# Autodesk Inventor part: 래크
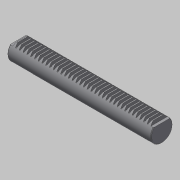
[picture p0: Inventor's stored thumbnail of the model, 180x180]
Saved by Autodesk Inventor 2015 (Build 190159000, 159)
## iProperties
Created: 2019-06
Part Number: 래크
Material: 스테인리스강
Document SubType Name: Modeling
Designer: mduedu
Density: 8.08 g/cm^3
Appearance: 기본값
Mass: 1739.85 g
Surface Area: 334.124 cm^2
Volume: 215.328 cm^3
Author: mduedu
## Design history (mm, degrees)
sketch "스케치1"
  geometry: L1 (0, 0)-(240, 0); L2 (240, 0)-(240, 34); L3 (240, 34)-(0, 34); L4 (0, 34)-(0, 0)
  constraints: 8 end point, 2 parallel, 1 horizontal, 1 perpendicular
  dimensions: "d0" = 240 distance of L1.start L1.end; "d1" = 34 distance of L1.end L2.end
extrude "돌출1" new body sketch "스케치1" stored distance "d2" = 36; taper "d3" = 0 deg
sketch "스케치2"
  geometry: L1 (0, 0)-(240, 0) reference; L2 (240, 0)-(240, 34) reference; L3 (240, 34)-(0, 34) reference; L4 (0, 34)-(0, 0) reference; L5 (9.44, 29.5)-(10.76, 29.5); L6 (12.398, 34)-(7.802, 34); L7 (10.1, 34)-(10.1, 29.5); L8 (7.802, 34)-(9.44, 29.5); L9 (12.398, 34)-(10.76, 29.5); L10 (8.53, 32)-(11.67, 32); 1 further point
  constraints: 12 end point, 2 midpoint, 2 point on line, 1 collinear, 1 horizontal, 1 parallel, 1 perpendicular, 1 symmetric about line
  dimensions: "d4" = 20 deg angle of L9 L7; "d5" = 2 distance between parallel lines of L10 L6; "d7" = 4.5 distance between parallel lines of L5 L6 (= 2.25 x d5); "d8" = 3.14 distance of L10.start L10.end; "d9" = 10.1 distance between parallel lines of L4 L7
extrude "돌출2" cut sketch "스케치2" stored distance "d10" = 36; taper "d11" = 0 deg
sketch "스케치3"
  geometry: L1 (235.52, 29.5)-(233.882, 34) reference; L2 (233.882, 34)-(232.198, 34) reference; L3 (232.198, 34)-(230.56, 29.5) reference; L4 (230.56, 29.5)-(229.24, 29.5) reference; L5 (229.24, 29.5)-(227.602, 34) reference; L6 (227.602, 34)-(225.918, 34) reference; L7 (225.918, 34)-(224.28, 29.5) reference; L8 (224.28, 29.5)-(222.96, 29.5) reference; L9 (222.96, 29.5)-(221.322, 34) reference; L10 (221.322, 34)-(219.638, 34) reference; L11 (219.638, 34)-(218, 29.5) reference; L12 (218, 29.5)-(216.68, 29.5) reference; L13 (216.68, 29.5)-(215.042, 34) reference; L14 (215.042, 34)-(213.358, 34) reference; L15 (213.358, 34)-(211.72, 29.5) reference; L16 (211.72, 29.5)-(210.4, 29.5) reference; L17 (210.4, 29.5)-(208.762, 34) reference; L18 (208.762, 34)-(207.078, 34) reference; L19 (207.078, 34)-(205.44, 29.5) reference; L20 (205.44, 29.5)-(204.12, 29.5) reference; L21 (204.12, 29.5)-(202.482, 34) reference; L22 (202.482, 34)-(200.798, 34) reference; L23 (200.798, 34)-(199.16, 29.5) reference; L24 (199.16, 29.5)-(197.84, 29.5) reference; L25 (197.84, 29.5)-(196.202, 34) reference; L26 (196.202, 34)-(194.518, 34) reference; L27 (194.518, 34)-(192.88, 29.5) reference; L28 (192.88, 29.5)-(191.56, 29.5) reference; L29 (191.56, 29.5)-(189.922, 34) reference; L30 (189.922, 34)-(188.238, 34) reference; L31 (188.238, 34)-(186.6, 29.5) reference; L32 (186.6, 29.5)-(185.28, 29.5) reference; L33 (185.28, 29.5)-(183.642, 34) reference; L34 (183.642, 34)-(181.958, 34) reference; L35 (181.958, 34)-(180.32, 29.5) reference; L36 (180.32, 29.5)-(179, 29.5) reference; L37 (179, 29.5)-(177.362, 34) reference; L38 (177.362, 34)-(175.678, 34) reference; L39 (175.678, 34)-(174.04, 29.5) reference; L40 (174.04, 29.5)-(172.72, 29.5) reference; L41 (172.72, 29.5)-(171.082, 34) reference; L42 (171.082, 34)-(169.398, 34) reference; L43 (169.398, 34)-(167.76, 29.5) reference; L44 (167.76, 29.5)-(166.44, 29.5) reference; L45 (166.44, 29.5)-(164.802, 34) reference; L46 (164.802, 34)-(163.118, 34) reference; L47 (163.118, 34)-(161.48, 29.5) reference; L48 (161.48, 29.5)-(160.16, 29.5) reference; L49 (160.16, 29.5)-(158.522, 34) reference; L50 (158.522, 34)-(156.838, 34) reference; L51 (156.838, 34)-(155.2, 29.5) reference; L52 (155.2, 29.5)-(153.88, 29.5) reference; L53 (153.88, 29.5)-(152.242, 34) reference; L54 (152.242, 34)-(150.558, 34) reference; L55 (150.558, 34)-(148.92, 29.5) reference; L56 (148.92, 29.5)-(147.6, 29.5) reference; L57 (147.6, 29.5)-(145.962, 34) reference; L58 (145.962, 34)-(144.278, 34) reference; L59 (144.278, 34)-(142.64, 29.5) reference; L60 (142.64, 29.5)-(141.32, 29.5) reference; L61 (141.32, 29.5)-(139.682, 34) reference; L62 (139.682, 34)-(137.998, 34) reference; L63 (137.998, 34)-(136.36, 29.5) reference; L64 (136.36, 29.5)-(135.04, 29.5) reference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; 1 further point
  constraints: 16 end point, 4 parallel, 2 horizontal, 2 perpendicular
extrude "돌출3" cut sketch "스케치3" stored distance "d18" = 36; taper "d19" = 0 deg
sketch "스케치4"
  geometry: L1 (4.48, 29.5)-(0, 29.5) reference; L2 (0, 29.5)-(0, 0) reference; L3 (0, 0)-(240, 0) reference; L4 (240, 0)-(240, 29.5) reference; L5 (240, 29.5)-(235.52, 29.5) reference; L6 (235.52, 29.5)-(233.882, 34) reference; L7 (233.882, 34)-(232.198, 34) reference; L8 (232.198, 34)-(230.56, 29.5) reference; L9 (230.56, 29.5)-(229.24, 29.5) reference; L10 (229.24, 29.5)-(227.602, 34) reference; L11 (227.602, 34)-(225.918, 34) reference; L12 (225.918, 34)-(224.28, 29.5) reference; L13 (224.28, 29.5)-(222.96, 29.5) reference; L14 (222.96, 29.5)-(221.322, 34) reference; L15 (221.322, 34)-(219.638, 34) reference; L16 (219.638, 34)-(218, 29.5) reference; L17 (218, 29.5)-(216.68, 29.5) reference; L18 (216.68, 29.5)-(215.042, 34) reference; L19 (215.042, 34)-(213.358, 34) reference; L20 (213.358, 34)-(211.72, 29.5) reference; L21 (211.72, 29.5)-(210.4, 29.5) reference; L22 (210.4, 29.5)-(208.762, 34) reference; L23 (208.762, 34)-(207.078, 34) reference; L24 (207.078, 34)-(205.44, 29.5) reference; L25 (205.44, 29.5)-(204.12, 29.5) reference; L26 (204.12, 29.5)-(202.482, 34) reference; L27 (202.482, 34)-(200.798, 34) reference; L28 (200.798, 34)-(199.16, 29.5) reference; L29 (199.16, 29.5)-(197.84, 29.5) reference; L30 (197.84, 29.5)-(196.202, 34) reference; L31 (196.202, 34)-(194.518, 34) reference; L32 (194.518, 34)-(192.88, 29.5) reference; L33 (192.88, 29.5)-(191.56, 29.5) reference; L34 (191.56, 29.5)-(189.922, 34) reference; L35 (189.922, 34)-(188.238, 34) reference; L36 (188.238, 34)-(186.6, 29.5) reference; L37 (186.6, 29.5)-(185.28, 29.5) reference; L38 (185.28, 29.5)-(183.642, 34) reference; L39 (183.642, 34)-(181.958, 34) reference; L40 (181.958, 34)-(180.32, 29.5) reference; L41 (180.32, 29.5)-(179, 29.5) reference; L42 (179, 29.5)-(177.362, 34) reference; L43 (177.362, 34)-(175.678, 34) reference; L44 (175.678, 34)-(174.04, 29.5) reference; L45 (174.04, 29.5)-(172.72, 29.5) reference; L46 (172.72, 29.5)-(171.082, 34) reference; L47 (171.082, 34)-(169.398, 34) reference; L48 (169.398, 34)-(167.76, 29.5) reference; L49 (167.76, 29.5)-(166.44, 29.5) reference; L50 (166.44, 29.5)-(164.802, 34) reference; L51 (164.802, 34)-(163.118, 34) reference; L52 (163.118, 34)-(161.48, 29.5) reference; L53 (161.48, 29.5)-(160.16, 29.5) reference; L54 (160.16, 29.5)-(158.522, 34) reference; L55 (158.522, 34)-(156.838, 34) reference; L56 (156.838, 34)-(155.2, 29.5) reference; L57 (155.2, 29.5)-(153.88, 29.5) reference; L58 (153.88, 29.5)-(152.242, 34) reference; L59 (152.242, 34)-(150.558, 34) reference; L60 (150.558, 34)-(148.92, 29.5) reference; L61 (148.92, 29.5)-(147.6, 29.5) reference; L62 (147.6, 29.5)-(145.962, 34) reference; L63 (145.962, 34)-(144.278, 34) reference; L64 (144.278, 34)-(142.64, 29.5) reference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; 1 further point
  constraints: 8 end point, 2 parallel, 1 horizontal, 1 perpendicular, 1 point on line
  dimensions: "d20" = 36 distance between parallel lines of L156 L2; "d21" = 10 distance between parallel lines of L4 L154; "d22" = 194 distance between parallel lines of L154 L156 (derived); "d23" = 4 distance between parallel lines of L3 L155
extrude "돌출4" cut sketch "스케치4" stored distance "d24" = 36; taper "d25" = 0 deg
sketch "스케치5"
  geometry: L1 (36, 0)-(0, 0) reference; C1 r 18 at (18, 18); 2 further points
  constraints: 1 centre point, 1 midpoint, 1 tangent, 1 vertical alignment
  dimensions: "d26" = 36 diameter of C1
extrude "돌출5" sketch "스케치5" stored distance "d27" = 36; taper "d28" = 0 deg
chamfer "모따기1" distance "d29" = 1; stored, may be unused: second distance "d30" = 2, angle "d31" = 45 deg
node "솔리드1"
pattern_linear "직사각형 패턴1" dims "d14" = 6.28, "d17" = 6.28
node "투영된 루프1"
node "투영된 루프2"
node "투영된 루프3"
